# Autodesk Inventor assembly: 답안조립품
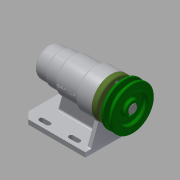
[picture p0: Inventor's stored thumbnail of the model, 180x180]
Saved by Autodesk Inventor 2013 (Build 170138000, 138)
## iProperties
Created: 2017-09
Part Number: 답안조립품
Document SubType Name: Assembly
Designer: Administrator
Author: Administrator
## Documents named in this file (12)
- C:\Users\Administrator\Desktop\470907V1004\답안조립품.iam
- C:\Users\Administrator\Desktop\470907V1004\본체.ipt
- C:\Users\Administrator\Desktop\470907V1004\공용부품\V벨트풀리.ipt
- C:\Users\Administrator\Desktop\470907V1004\공용부품\멈춤나사 M3x8.ipt
- C:\Users\Administrator\Desktop\470907V1004\공용부품\베어링 6004.ipt
- C:\Users\Administrator\Desktop\470907V1004\공용부품\베어링 51202.ipt
- C:\Users\Administrator\Desktop\470907V1004\공용부품\볼트 M4 x 12.ipt
- C:\Users\Administrator\Desktop\470907V1004\공용부품\어댑터슬리브.ipt
- C:\Users\Administrator\Desktop\470907V1004\공용부품\오일 실 20x35x7.ipt
- C:\Users\Administrator\Desktop\470907V1004\공용부품\축.ipt
- C:\Users\Administrator\Desktop\470907V1004\공용부품\커버.ipt
- C:\Users\Administrator\Desktop\470907V1004\공용부품\키 5 x 5 x 16.ipt
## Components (1 placed, 1 different names)
1. V벨트풀리:1 — 플러쉬:1
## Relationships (1: Flush 1)
- 플러쉬:1 [Flush]: V벨트풀리:1
